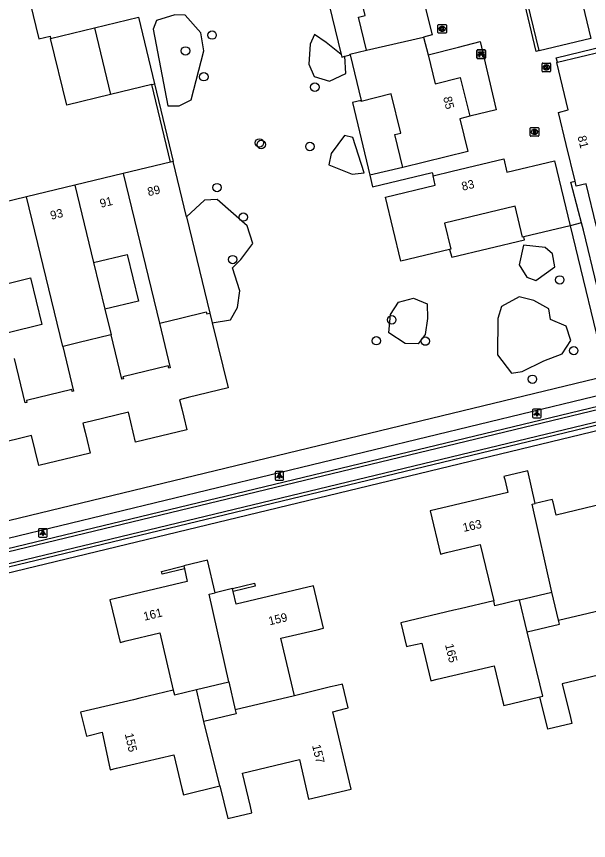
# Model space of a CAD drawing. Extents: x 156664 to 157568, y 383571 to 384421.
# Drawn here: x 156893.1 to 156959.8, y 383982.4 to 384078.5 of the extents above; entities that cross this region are included whole.
import ezdxf

# ---------------------------------------------------------------- set-up
doc = ezdxf.new("R2010")
doc.units = 0
for name, color, linetype in [('IMGEO_Bank', 7, 'Continuous'), ('IMGEO_Boom', 7, 'Continuous'), ('IMGEO_Groenvoorziening', 7, 'Continuous'), ('IMGEO_Hek', 7, 'Continuous'), ('IMGEO_Kolk', 7, 'Continuous'), ('IMGEO_Lichtpunt', 7, 'Continuous'), ('IMGEO_Muur', 7, 'Continuous'), ('IMGEO_Pand', 7, 'Continuous'), ('IMGEO_Pand_nummerreeks', 7, 'Continuous'), ('IMGEO_Rijbaan_lokaal_open', 7, 'Continuous'), ('IMGEO_Rioolput', 7, 'Continuous'), ('IMGEO_Voetpad_open', 7, 'Continuous'), ('IMGEO_Waterloop', 7, 'Continuous')]:
    doc.layers.add(name, color=color, linetype=linetype)

msp = doc.modelspace()

# ---------------------------------------------------------------- linework, layer by layer
at = {"layer": 'IMGEO_Bank'}
for p, q in [((156946.784, 384073.642), (156946.784, 384074.483)), ((156946.784, 384074.483), (156946.784, 384073.642)), ((156946.859, 384074.567), (156947.7, 384074.567)), ((156947.7, 384074.567), (156946.859, 384074.567)), ((156947.784, 384074.492), (156947.784, 384073.651)), ((156947.784, 384073.651), (156947.784, 384074.492)), ((156947.709, 384073.567), (156946.868, 384073.567)), ((156946.868, 384073.567), (156947.709, 384073.567)), ((156947.481, 384073.965), (156947.088, 384073.965)), ((156947.093, 384074.073), (156947.093, 384074.179)), ((156947.137, 384074.179), (156947.137, 384074.073)), ((156947.425, 384074.185), (156947.143, 384074.185)), ((156947.143, 384074.067), (156947.425, 384074.067)), ((156947.431, 384074.073), (156947.431, 384074.179)), ((156947.475, 384074.179), (156947.475, 384074.073))]:
    msp.add_line(p, q, dxfattribs=at)
for points in [[(156947.087, 384074.185), (156947.001, 384074.185), (156947.001, 384074.346), (156947.564, 384074.346), (156947.564, 384074.185), (156947.481, 384074.185)], [(156947.031, 384073.965), (156946.889, 384073.965), (156947.001, 384074.067), (156947.087, 384074.067)], [(156947.081, 384073.958), (156947.081, 384073.751), (156947.038, 384073.751), (156947.038, 384073.958)], [(156947.481, 384074.067), (156947.564, 384074.067), (156947.676, 384073.965), (156947.537, 384073.965)], [(156947.531, 384073.958), (156947.531, 384073.751), (156947.487, 384073.751), (156947.487, 384073.958)]]:
    msp.add_lwpolyline(points, dxfattribs=at)
for centre, radius, start, end in [((156946.862, 384074.489), 0.0779, 92.4484, 184.28452), ((156946.862, 384074.489), 0.0779, 92.4484, 184.28452), ((156947.706, 384074.489), 0.0779, 2.4484, 94.28452), ((156947.706, 384074.489), 0.0779, 2.4484, 94.28452), ((156946.862, 384073.645), 0.0779, 182.4484, 274.28452), ((156946.862, 384073.645), 0.0779, 182.4484, 274.28452), ((156947.031, 384073.958), 0.00671, 2.89567, 87.10433), ((156947.088, 384073.958), 0.00671, 92.89567, 177.10433), ((156947.086, 384074.178), 0.00671, 2.89567, 87.10433), ((156947.086, 384074.074), 0.00671, 272.89567, 357.10433), ((156947.143, 384074.178), 0.00671, 92.89567, 177.10433), ((156947.143, 384074.074), 0.00671, 182.89567, 267.10433), ((156947.425, 384074.178), 0.00671, 2.89567, 87.10433), ((156947.425, 384074.074), 0.00671, 272.89567, 357.10433), ((156947.482, 384074.178), 0.00671, 92.89567, 177.10433), ((156947.482, 384074.074), 0.00671, 182.89567, 267.10433), ((156947.48, 384073.958), 0.00671, 2.89567, 87.10433), ((156947.537, 384073.958), 0.00671, 92.89567, 177.10433), ((156947.706, 384073.645), 0.0779, 272.4484, 4.28452), ((156947.706, 384073.645), 0.0779, 272.4484, 4.28452)]:
    msp.add_arc(centre, radius, start, end, dxfattribs=at)
at = {"layer": 'IMGEO_Boom'}
for centre in [(156915.901, 384076.293), (156912.798, 384074.447), (156914.934, 384071.441), (156927.885, 384070.223), (156921.414, 384063.72), (156921.633, 384063.538), (156927.314, 384063.308), (156916.474, 384058.513), (156919.542, 384055.075), (156918.299, 384050.124), (156956.457, 384047.755), (156936.859, 384043.095), (156935.058, 384040.661), (156940.769, 384040.611), (156958.083, 384039.502), (156953.261, 384036.162)]:
    msp.add_circle(centre, 0.489, dxfattribs=at)
at = {"layer": 'IMGEO_Groenvoorziening'}
for points in [[(156932.249, 384084.864), (156928.555, 384083.965), (156930.939, 384074.036)], [(156909.039, 384076.974), (156910.731, 384068.042), (156912.048, 384068.041), (156913.46, 384068.754), (156914.948, 384074.472), (156914.591, 384076.577), (156912.77, 384078.626), (156911.571, 384078.659), (156909.402, 384078), (156909.039, 384076.974)], [(156930.939, 384074.036), (156929.215, 384075.434), (156927.86, 384076.367), (156927.327, 384075.229), (156927.188, 384072.915), (156927.808, 384071.475), (156929.611, 384070.922), (156931.493, 384071.828), (156931.381, 384073.823)], [(156930.939, 384074.036), (156931.014, 384073.724), (156931.381, 384073.823)], [(156931.381, 384073.823), (156931.993, 384073.988)], [(156933.275, 384068.671), (156932.258, 384068.433), (156934.279, 384059.95)], [(156932.296, 384064.374), (156931.353, 384064.601), (156929.804, 384062.481), (156929.523, 384061.161), (156932.242, 384060.074), (156933.639, 384060.251), (156932.296, 384064.374)], [(156915.921, 384042.738), (156918.035, 384043.088), (156918.85, 384044.543), (156919.13, 384046.461), (156918.286, 384049.149), (156919.243, 384050.149), (156920.639, 384051.978), (156919.981, 384054.073), (156916.475, 384057.141), (156915.018, 384057.055), (156912.923, 384055.115)], [(156943.607, 384051.308), (156943.875, 384050.383), (156952.343, 384052.441), (156952.269, 384052.774)], [(156955.874, 384049.265), (156955.61, 384050.801), (156954.764, 384051.528), (156952.207, 384051.818), (156951.717, 384049.501), (156952.626, 384048.08), (156953.666, 384047.687), (156955.874, 384049.265)], [(156940.984, 384044.968), (156941.01, 384043.268), (156940.743, 384041.394), (156939.929, 384040.311), (156938.429, 384040.322), (156936.53, 384041.566), (156936.719, 384043.715), (156937.643, 384045.166), (156939.381, 384045.609), (156940.984, 384044.968)], [(156953.43, 384045.361), (156951.715, 384045.785), (156949.656, 384044.668), (156949.22, 384043.269), (156949.194, 384039.026), (156950.812, 384036.892), (156952.075, 384037.058), (156954.606, 384038.321), (156956.739, 384039.127), (156957.735, 384040.673), (156957.198, 384042.349), (156955.381, 384043.138), (156955.194, 384044.378), (156953.43, 384045.361)], [(156915.646, 384043.875), (156915.921, 384042.738)], [(156915.921, 384042.738), (156917.757, 384035.153), (156913.096, 384034.024), (156912.116, 384033.784), (156912.375, 384032.716), (156912.602, 384031.739), (156912.958, 384030.282), (156906.969, 384028.837), (156906.132, 384032.322), (156901.828, 384031.282), (156900.84, 384031.048), (156901.096, 384029.983), (156901.33, 384029.013), (156901.684, 384027.555), (156895.702, 384026.104), (156894.839, 384029.59), (156890.551, 384028.557)], [(156861.913, 384009.165), (156971.048, 384035.487)], [(156965.9, 383938.498), (157002.117, 383942.318), (156972.167, 384033.813), (156964.844, 384031.779), (156863.418, 384007.321)], [(156953.099, 383937.896), (156882.007, 383929.988), (156863.465, 384006.689), (156971.911, 384032.865), (156984.848, 383993.384), (157001.305, 383943.16), (156963.71, 383939.037)]]:
    msp.add_lwpolyline(points, dxfattribs=at)
at = {"layer": 'IMGEO_Hek'}
msp.add_lwpolyline([(156953.099, 383937.896), (156882.007, 383929.988), (156863.465, 384006.689), (156971.911, 384032.865), (156984.848, 383993.384), (157001.305, 383943.16)], dxfattribs=at)
at = {"layer": 'IMGEO_Kolk'}
for p, q in [((156942.232, 384076.592), (156942.232, 384077.444)), ((156942.307, 384077.518), (156943.159, 384077.518)), ((156942.72, 384077.298), (156942.745, 384077.298)), ((156943.233, 384077.444), (156943.233, 384076.592)), ((156943.159, 384076.518), (156942.307, 384076.518)), ((156942.743, 384076.738), (156942.718, 384076.738)), ((156954.386, 384072.103), (156954.386, 384072.955)), ((156954.461, 384073.029), (156955.313, 384073.029)), ((156954.874, 384072.809), (156954.899, 384072.809)), ((156955.387, 384072.955), (156955.387, 384072.103)), ((156955.313, 384072.029), (156954.461, 384072.029)), ((156954.897, 384072.249), (156954.872, 384072.249))]:
    msp.add_line(p, q, dxfattribs=at)
for points in [[(156942.232, 384076.592), (156942.232, 384077.444)], [(156942.307, 384077.518), (156943.159, 384077.518)], [(156942.553, 384077.218), (156942.676, 384077.218), (156942.676, 384077.067), (156942.806, 384077.218), (156942.97, 384077.218), (156942.824, 384077.067), (156942.977, 384076.818), (156942.825, 384076.818), (156942.74, 384076.982), (156942.676, 384076.915), (156942.676, 384076.818), (156942.553, 384076.818), (156942.553, 384077.218)], [(156943.233, 384077.444), (156943.233, 384076.592)], [(156943.159, 384076.518), (156942.307, 384076.518)], [(156954.386, 384072.103), (156954.386, 384072.955)], [(156954.461, 384073.029), (156955.313, 384073.029)], [(156954.707, 384072.729), (156954.83, 384072.729), (156954.83, 384072.578), (156954.96, 384072.729), (156955.124, 384072.729), (156954.978, 384072.578), (156955.131, 384072.329), (156954.979, 384072.329), (156954.894, 384072.493), (156954.83, 384072.426), (156954.83, 384072.329), (156954.707, 384072.329), (156954.707, 384072.729)], [(156955.387, 384072.955), (156955.387, 384072.103)], [(156955.313, 384072.029), (156954.461, 384072.029)]]:
    msp.add_lwpolyline(points, dxfattribs=at)
for centre, start, end in [((156942.309, 384077.442), 91.55205, 178.44795), ((156942.309, 384077.442), 91.55205, 178.44795), ((156943.157, 384077.442), 1.55205, 88.44795), ((156943.157, 384077.442), 1.55205, 88.44795), ((156942.309, 384076.594), 181.55205, 268.44795), ((156942.309, 384076.594), 181.55205, 268.44795), ((156943.157, 384076.594), 271.55205, 358.44795), ((156943.157, 384076.594), 271.55205, 358.44795), ((156954.463, 384072.953), 91.55205, 178.44795), ((156954.463, 384072.953), 91.55205, 178.44795), ((156955.311, 384072.953), 1.55205, 88.44795), ((156955.311, 384072.953), 1.55205, 88.44795), ((156954.463, 384072.105), 181.55205, 268.44795), ((156954.463, 384072.105), 181.55205, 268.44795), ((156955.311, 384072.105), 271.55205, 358.44795), ((156955.311, 384072.105), 271.55205, 358.44795)]:
    msp.add_arc(centre, 0.0765, start, end, dxfattribs=at)
for centre, major_axis, ratio, start_param, end_param in [((156942.719, 384077.018), (-0.387, 0.002), 0.722429, 4.712389, 7.853982), ((156942.744, 384077.018), (-0.39, 0.002), 0.717154, 1.570796, 4.712389), ((156954.873, 384072.529), (-0.387, 0.002), 0.722429, 4.712389, 7.853982), ((156954.898, 384072.529), (-0.39, 0.002), 0.717154, 1.570796, 4.712389)]:
    msp.add_ellipse(centre, major_axis=major_axis, ratio=ratio, start_param=start_param, end_param=end_param, dxfattribs=at)
at = {"layer": 'IMGEO_Lichtpunt'}
for p, q in [((156953.291, 384032.587), (156953.291, 384031.78)), ((156953.291, 384032.587), (156953.291, 384031.78)), ((156954.193, 384032.682), (156953.385, 384032.682)), ((156954.193, 384032.682), (156953.385, 384032.682)), ((156954.287, 384031.78), (156954.287, 384032.587)), ((156954.287, 384031.78), (156954.287, 384032.587)), ((156953.385, 384031.686), (156954.193, 384031.686)), ((156953.385, 384031.686), (156954.193, 384031.686)), ((156923.251, 384025.305), (156923.251, 384024.498)), ((156923.251, 384025.305), (156923.251, 384024.498)), ((156924.153, 384025.4), (156923.345, 384025.4)), ((156924.153, 384025.4), (156923.345, 384025.4)), ((156924.247, 384024.498), (156924.247, 384025.305)), ((156924.247, 384024.498), (156924.247, 384025.305)), ((156923.345, 384024.404), (156924.153, 384024.404)), ((156923.345, 384024.404), (156924.153, 384024.404)), ((156895.667, 384018.65), (156895.667, 384017.843)), ((156895.667, 384018.65), (156895.667, 384017.843)), ((156896.569, 384018.745), (156895.761, 384018.745)), ((156896.569, 384018.745), (156895.761, 384018.745)), ((156896.663, 384017.843), (156896.663, 384018.65)), ((156896.663, 384017.843), (156896.663, 384018.65)), ((156895.761, 384017.749), (156896.569, 384017.749)), ((156895.761, 384017.749), (156896.569, 384017.749))]:
    msp.add_line(p, q, dxfattribs=at)
for points in [[(156953.665, 384032.251), (156953.704, 384032.223), (156953.516, 384031.961), (156953.478, 384031.988), (156953.665, 384032.251)], [(156953.767, 384032.203), (156953.814, 384032.203), (156953.814, 384031.881), (156953.767, 384031.881), (156953.767, 384032.203)], [(156953.877, 384032.223), (156953.915, 384032.25), (156954.102, 384031.988), (156954.063, 384031.96), (156953.877, 384032.223)], [(156923.625, 384024.969), (156923.664, 384024.941), (156923.476, 384024.679), (156923.438, 384024.706), (156923.625, 384024.969)], [(156923.727, 384024.921), (156923.774, 384024.921), (156923.774, 384024.599), (156923.727, 384024.599), (156923.727, 384024.921)], [(156923.837, 384024.941), (156923.875, 384024.968), (156924.062, 384024.706), (156924.023, 384024.678), (156923.837, 384024.941)], [(156896.041, 384018.314), (156896.08, 384018.286), (156895.892, 384018.024), (156895.854, 384018.051), (156896.041, 384018.314)], [(156896.143, 384018.266), (156896.19, 384018.266), (156896.19, 384017.944), (156896.143, 384017.944), (156896.143, 384018.266)], [(156896.253, 384018.286), (156896.291, 384018.313), (156896.478, 384018.051), (156896.439, 384018.023), (156896.253, 384018.286)]]:
    msp.add_lwpolyline(points, dxfattribs=at)
for centre in [(156953.79, 384032.385), (156923.75, 384025.103), (156896.166, 384018.448)]:
    msp.add_circle(centre, 0.0994, dxfattribs=at)
for centre, start, end in [((156953.385, 384032.587), 90, 180), ((156953.385, 384032.587), 90, 180), ((156954.193, 384032.587), 0, 90), ((156954.193, 384032.587), 0, 90), ((156953.385, 384031.78), 180, 270), ((156953.385, 384031.78), 180, 270), ((156954.193, 384031.78), 270, 0), ((156954.193, 384031.78), 270, 360), ((156923.345, 384025.305), 90, 180), ((156923.345, 384025.305), 90, 180), ((156924.153, 384025.305), 0, 90), ((156924.153, 384025.305), 0, 90), ((156923.345, 384024.498), 180, 270), ((156923.345, 384024.498), 180, 270), ((156924.153, 384024.498), 270, 0), ((156924.153, 384024.498), 270, 360), ((156895.761, 384018.65), 90, 180), ((156895.761, 384018.65), 90, 180), ((156896.569, 384018.65), 0, 90), ((156896.569, 384018.65), 0, 90), ((156895.761, 384017.843), 180, 270), ((156895.761, 384017.843), 180, 270), ((156896.569, 384017.843), 270, 0), ((156896.569, 384017.843), 270, 360)]:
    msp.add_arc(centre, 0.0946, start, end, dxfattribs=at)
at = {"layer": 'IMGEO_Muur'}
for points in [[(156911.037, 384061.496), (156908.853, 384070.547)], [(156909.174, 384070.626), (156911.358, 384061.574)], [(156912.673, 384014.043), (156910.092, 384013.43), (156910.01, 384013.767), (156912.592, 384014.397)], [(156918.277, 384011.753), (156920.854, 384012.373), (156920.936, 384012.033), (156918.359, 384011.413)]]:
    msp.add_lwpolyline(points, dxfattribs=at)
at = {"layer": 'IMGEO_Pand'}
for points in [[(156933.906, 384074.537), (156932.99, 384078.392), (156933.768, 384078.586), (156932.249, 384084.864)], [(156954.047, 384074.482), (156952.377, 384081.427), (156954.516, 384081.941), (156953.681, 384085.38)], [(156963.163, 384084.034), (156958.41, 384082.88), (156960.083, 384075.91)], [(156945.461, 384081.373), (156940.609, 384080.187), (156941.558, 384076.308), (156940.57, 384076.066)], [(156902.171, 384077.153), (156907.31, 384078.397), (156909.174, 384070.626)], [(156897.057, 384075.914), (156902.171, 384077.153)], [(156902.171, 384077.153), (156904.052, 384069.376)], [(156904.052, 384069.376), (156898.943, 384068.13), (156897.057, 384075.914)], [(156933.906, 384074.537), (156940.57, 384076.066)], [(156940.57, 384076.066), (156941.086, 384074.007)], [(156960.083, 384075.91), (156954.056, 384074.446), (156954.047, 384074.482)], [(156931.993, 384073.988), (156931.973, 384074.071), (156933.906, 384074.537)], [(156956.182, 384073.121), (156964.005, 384075.018), (156965.305, 384069.632)], [(156931.993, 384073.988), (156933.275, 384068.671)], [(156941.086, 384074.007), (156941.936, 384070.617), (156944.852, 384071.347), (156945.951, 384066.823)], [(156958.236, 384059.261), (156957.199, 384063.543), (156956.296, 384067.286), (156957.449, 384067.563), (156956.119, 384073.106), (156956.182, 384073.121)], [(156908.853, 384070.547), (156904.052, 384069.376)], [(156908.853, 384070.547), (156909.174, 384070.626)], [(156938.142, 384060.86), (156937.21, 384064.69), (156937.909, 384064.859), (156936.794, 384069.462), (156933.304, 384068.552), (156933.275, 384068.671)], [(156945.951, 384066.823), (156944.796, 384066.546), (156945.72, 384062.703), (156938.142, 384060.86)], [(156941.675, 384059.88), (156943.889, 384060.413), (156949.912, 384061.866), (156950.278, 384060.318), (156955.834, 384061.641), (156957.651, 384054.07)], [(156911.037, 384061.496), (156905.536, 384060.164)], [(156911.358, 384061.574), (156911.037, 384061.496)], [(156912.923, 384055.115), (156911.358, 384061.574)], [(156905.536, 384060.164), (156899.898, 384058.798)], [(156905.536, 384060.164), (156909.757, 384042.712)], [(156943.607, 384051.308), (156937.932, 384049.945), (156936.129, 384057.408), (156941.935, 384058.813), (156941.675, 384059.88)], [(156964.031, 384054.789), (156960.738, 384053.996), (156959.551, 384058.947), (156958.379, 384058.672), (156958.236, 384059.261)], [(156899.898, 384058.798), (156894.26, 384057.432)], [(156899.898, 384058.798), (156902.082, 384049.769)], [(156894.26, 384057.432), (156888.622, 384056.067)], [(156898.483, 384039.975), (156894.26, 384057.432)], [(156952.269, 384052.774), (156952.113, 384052.736), (156951.245, 384056.344), (156943.017, 384054.348), (156943.754, 384051.343), (156943.607, 384051.308)], [(156912.923, 384055.115), (156915.646, 384043.875)], [(156957.651, 384054.07), (156952.269, 384052.774)], [(156902.082, 384049.769), (156905.985, 384050.712), (156907.306, 384045.271), (156903.4, 384044.321)], [(156902.082, 384049.769), (156903.4, 384044.321)], [(156890.807, 384047.038), (156894.71, 384047.98), (156896.031, 384042.54), (156892.125, 384041.59)], [(156903.4, 384044.321), (156904.116, 384041.361)], [(156909.757, 384042.712), (156909.946, 384042.758), (156912.207, 384043.307), (156915.222, 384044.038), (156915.292, 384043.78), (156915.646, 384043.875)], [(156909.757, 384042.712), (156911.014, 384037.513), (156910.848, 384037.468), (156910.782, 384037.717), (156905.504, 384036.445), (156905.565, 384036.209), (156905.374, 384036.16), (156904.116, 384041.361)], [(156904.116, 384041.361), (156903.941, 384041.318), (156900.386, 384040.443), (156898.672, 384040.021), (156898.483, 384039.975)], [(156898.483, 384039.975), (156899.739, 384034.784), (156899.571, 384034.743), (156899.522, 384034.965), (156894.235, 384033.695), (156894.286, 384033.473), (156894.099, 384033.43), (156892.851, 384038.588)], [(156953.573, 384021.686), (156952.723, 384025.492), (156949.947, 384024.83), (156950.028, 384024.49), (156950.39, 384022.967), (156941.341, 384020.832), (156942.531, 384015.79), (156943.26, 384015.964), (156947.186, 384016.898), (156948.744, 384010.349)], [(156963.215, 384009.708), (156961.597, 384016.497), (156965.498, 384017.423), (156966.228, 384017.596), (156965.068, 384022.482), (156956.02, 384020.334), (156955.666, 384021.823), (156955.58, 384022.162), (156953.573, 384021.686)], [(156955.534, 384011.329), (156953.24, 384021.607), (156953.573, 384021.686)], [(156916.275, 384011.271), (156915.362, 384015.063), (156912.592, 384014.397)], [(156912.673, 384014.043), (156913.007, 384012.58), (156903.98, 384010.431), (156905.169, 384005.492), (156905.869, 384005.663), (156909.797, 384006.588), (156911.371, 383999.903)], [(156912.592, 384014.397), (156912.673, 384014.043)], [(156925.516, 383999.261), (156923.932, 384005.961), (156928.156, 384006.96), (156928.886, 384007.132), (156927.715, 384012.082), (156918.71, 384009.954), (156918.359, 384011.413)], [(156917.835, 384000.881), (156915.554, 384011.101), (156916.275, 384011.271)], [(156918.277, 384011.753), (156916.275, 384011.271)], [(156918.359, 384011.413), (156918.277, 384011.753)], [(156951.768, 384010.44), (156955.534, 384011.329)], [(156963.215, 384009.708), (156967.085, 384010.737), (156967.81, 384010.93), (156968.383, 384011.082), (156969.116, 384008.328), (156968.77, 384008.236), (156967.292, 384007.843), (156969.467, 383998.785), (156964.543, 383997.613), (156964.362, 383998.324), (156963.434, 384002.24), (156956.738, 384000.639), (156957.699, 383996.722), (156957.859, 383996.021), (156955.07, 383995.352), (156954.146, 383999.13)], [(156956.304, 384008.064), (156955.534, 384011.329)], [(156948.744, 384010.349), (156944.818, 384009.415), (156944.089, 384009.242), (156937.901, 384007.773), (156938.557, 384005.007), (156938.899, 384005.083), (156940.377, 384005.409), (156941.431, 384001.012), (156942.162, 384001.182), (156948.808, 384002.759), (156949.75, 383998.866), (156949.927, 383998.137), (156954.146, 383999.13)], [(156951.768, 384010.44), (156948.885, 384009.754), (156948.744, 384010.349)], [(156952.648, 384006.711), (156951.768, 384010.44)], [(156956.304, 384008.064), (156963.215, 384009.708)], [(156952.648, 384006.711), (156956.414, 384007.6), (156956.304, 384008.064)], [(156954.146, 383999.13), (156954.483, 383999.209), (156952.648, 384006.711)], [(156914.069, 383999.992), (156917.835, 384000.881)], [(156916.819, 383988.763), (156917.746, 383984.953), (156920.536, 383985.617), (156920.361, 383986.346), (156919.43, 383990.235), (156926.075, 383991.826), (156926.975, 383987.922), (156927.143, 383987.191), (156932.112, 383988.386), (156929.974, 383997.404), (156931.443, 383997.774), (156931.783, 383997.86), (156931.108, 384000.625), (156930.457, 384000.467), (156929.728, 384000.289), (156925.516, 383999.261)], [(156917.835, 384000.881), (156918.605, 383997.617)], [(156911.371, 383999.903), (156907.451, 383998.973), (156906.742, 383998.805), (156900.567, 383997.336), (156901.232, 383994.556), (156901.571, 383994.642), (156903.061, 383995.018), (156904.018, 383990.637), (156904.758, 383990.806), (156911.451, 383992.383), (156912.38, 383988.441), (156912.552, 383987.711), (156916.819, 383988.763)], [(156911.371, 383999.903), (156911.496, 383999.38), (156914.069, 383999.992)], [(156914.949, 383996.263), (156914.069, 383999.992)], [(156925.516, 383999.261), (156918.605, 383997.617)], [(156918.605, 383997.617), (156918.715, 383997.152), (156914.949, 383996.263)], [(156916.819, 383988.763), (156914.949, 383996.263)]]:
    msp.add_lwpolyline(points, dxfattribs=at)
at = {"layer": 'IMGEO_Rijbaan_lokaal_open'}
for points in [[(156893.311, 384085.637), (156895.679, 384075.854), (156897.002, 384076.155), (156897.057, 384075.914)], [(156954.047, 384074.482), (156953.688, 384074.389), (156952.038, 384081.474), (156951.183, 384084.738), (156953.681, 384085.38)], [(156956.182, 384073.121), (156956.046, 384073.649), (156971.872, 384077.482)], [(156941.086, 384074.007), (156944.634, 384074.898), (156947.16, 384075.531), (156949.042, 384067.577), (156945.951, 384066.823)], [(156938.142, 384060.86), (156934.279, 384059.95)], [(156934.279, 384059.95), (156934.593, 384058.597), (156941.578, 384060.276), (156941.675, 384059.88)], [(156958.99, 384054.392), (156958.637, 384055.725), (156957.756, 384059.151), (156958.236, 384059.261)], [(156958.99, 384054.392), (156957.651, 384054.07)]]:
    msp.add_lwpolyline(points, dxfattribs=at)
at = {"layer": 'IMGEO_Rioolput'}
for p, q in [((156952.997, 384064.579), (156952.997, 384065.431)), ((156953.072, 384065.505), (156953.924, 384065.505)), ((156953.508, 384064.725), (156953.483, 384064.725)), ((156953.485, 384065.285), (156953.51, 384065.285)), ((156953.998, 384065.431), (156953.998, 384064.579)), ((156953.924, 384064.505), (156953.072, 384064.505))]:
    msp.add_line(p, q, dxfattribs=at)
for points in [[(156952.997, 384064.579), (156952.997, 384065.431)], [(156953.072, 384065.505), (156953.924, 384065.505)], [(156953.586, 384065.203), (156953.334, 384065.205), (156953.334, 384064.805)], [(156953.334, 384064.805), (156953.458, 384064.805), (156953.458, 384064.967), (156953.469, 384064.967)], [(156953.512, 384065.124), (156953.458, 384065.124), (156953.458, 384065.043)], [(156953.458, 384065.043), (156953.51, 384065.043)], [(156953.516, 384064.938), (156953.587, 384064.805), (156953.727, 384064.805), (156953.662, 384064.931)], [(156953.998, 384065.431), (156953.998, 384064.579)], [(156953.924, 384064.505), (156953.072, 384064.505)]]:
    msp.add_lwpolyline(points, dxfattribs=at)
for centre, radius, start, end in [((156953.074, 384065.429), 0.0765, 91.55205, 178.44795), ((156953.074, 384065.429), 0.0765, 91.55205, 178.44795), ((156953.468, 384064.914), 0.0533, 26.02933, 88.69889), ((156953.494, 384065.232), 0.19, 274.7715, 282.96867), ((156953.518, 384065.028), 0.0964, 77.00612, 93.18647), ((156953.532, 384065.085), 0.0378, 276.66336, 79.67722), ((156953.585, 384065.093), 0.109, 350.36119, 89.41601), ((156953.583, 384065.093), 0.112, 277.58423, 350.98172), ((156953.567, 384064.878), 0.108, 29.51342, 73.79051), ((156953.922, 384065.429), 0.0765, 1.55205, 88.44795), ((156953.922, 384065.429), 0.0765, 1.55205, 88.44795), ((156953.074, 384064.581), 0.0765, 181.55205, 268.44795), ((156953.074, 384064.581), 0.0765, 181.55205, 268.44795), ((156953.922, 384064.581), 0.0765, 271.55205, 358.44795), ((156953.922, 384064.581), 0.0765, 271.55205, 358.44795)]:
    msp.add_arc(centre, radius, start, end, dxfattribs=at)
for centre, major_axis, ratio, start_param, end_param in [((156953.484, 384065.005), (-0.387, 0.002), 0.722429, 4.712389, 7.853982), ((156953.509, 384065.005), (-0.39, 0.002), 0.717154, 1.570796, 4.712389)]:
    msp.add_ellipse(centre, major_axis=major_axis, ratio=ratio, start_param=start_param, end_param=end_param, dxfattribs=at)
at = {"layer": 'IMGEO_Voetpad_open'}
for points in [[(156960.817, 384046.955), (156959.212, 384053.553), (156958.99, 384054.392)], [(156957.651, 384054.07), (156961.888, 384036.567)], [(156855.447, 384008.779), (156971.462, 384036.848)], [(156854.988, 384010.73), (156961.888, 384036.567)]]:
    msp.add_lwpolyline(points, dxfattribs=at)
at = {"layer": 'IMGEO_Waterloop'}
for points in [[(156971.146, 384035.093), (156862.02, 384008.774)], [(156863.303, 384007.711), (156964.742, 384032.172), (156972.432, 384034.308), (157002.659, 383941.967), (156965.949, 383938.095)]]:
    msp.add_lwpolyline(points, dxfattribs=at)

# ---------------------------------------------------------------- texts
at = {"layer": 'IMGEO_Pand_nummerreeks'}
for s, rotation, p in [('85', 283.65337, (156942.846, 384069.014)), ('81', 283.5617, (156958.523, 384064.453)), ('83', 13.56191, (156945.127, 384058.14)), ('89', 13.61921, (156908.491, 384057.505)), ('91', 13.61921, (156902.931, 384056.158)), ('93', 13.61921, (156897.152, 384054.758)), ('163', 12.58, (156945.254, 384018.364)), ('161', 13.46709, (156908.007, 384008.006)), ('159', 13.19535, (156922.594, 384007.469)), ('165', 283.38769, (156943.063, 384005.211)), ('155', 282.95674, (156905.709, 383994.796)), ('157', 283.44841, (156927.555, 383993.46))]:
    msp.add_text(s, height=1, rotation=rotation, dxfattribs=at).set_placement(p)

doc.saveas('drawing.dxf')
